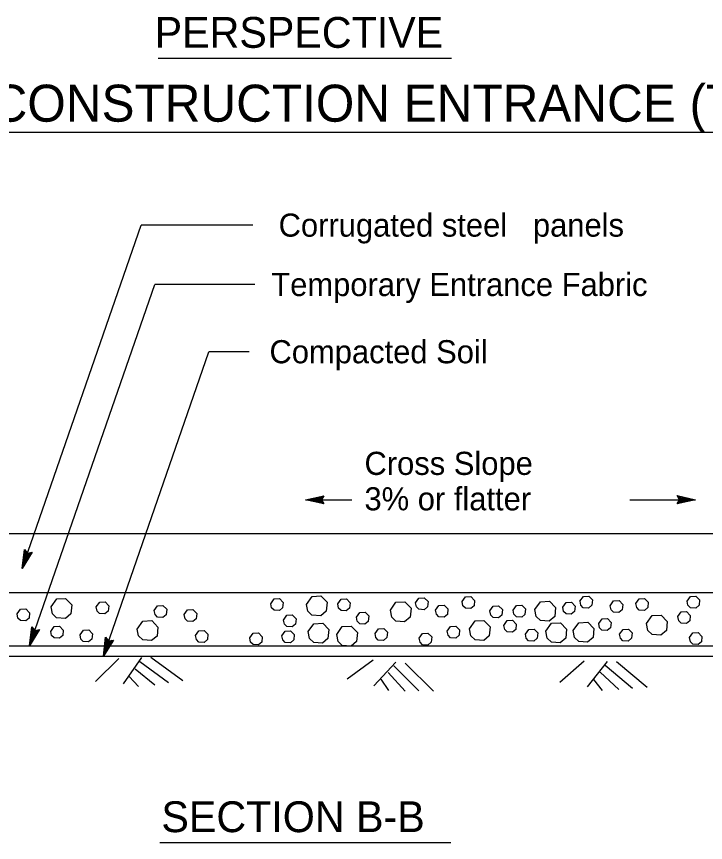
# Model space of a CAD drawing. Extents: x 6707406 to 6714471, y 1868570 to 1872341.
# Drawn here: x 6709685 to 6709899.6, y 1869786.1 to 1870043.3 of the extents above; entities that cross this region are included whole.
import ezdxf

# ---------------------------------------------------------------- set-up
doc = ezdxf.new("R2010")
doc.units = 0
for name, color, linetype in [('56 Stg 3 Anno', 7, 'Continuous'), ('57 Undefined', 7, 'Continuous'), ('59 Soundwall Ann', 7, 'Continuous'), ('60 Nongeo Data', 7, 'Continuous')]:
    doc.layers.add(name, color=color, linetype=linetype)

msp = doc.modelspace()

# ---------------------------------------------------------------- linework, layer by layer
at = {"layer": '56 Stg 3 Anno'}
for p, q in [((6709686.82, 1869871.46), (6709723.89, 1869978.35)), ((6709758.69, 1869978.35), (6709723.89, 1869978.35)), ((6709689.11, 1869847.39), (6709728.11, 1869959.86)), ((6709759.28, 1869959.86), (6709728.11, 1869959.86)), ((6709712.09, 1869844.14), (6709744.96, 1869938.93)), ((6709757.48, 1869938.93), (6709744.96, 1869938.93)), ((6709775.02, 1869892.82), (6709780.78, 1869894.1)), ((6709775.02, 1869892.82), (6709789.5, 1869892.82)), ((6709780.78, 1869891.53), (6709775.02, 1869892.82)), ((6709775.02, 1869892.82), (6709775.02, 1869892.82)), ((6709780.57, 1869891.87), (6709776.35, 1869892.82)), ((6709776.36, 1869892.82), (6709780.56, 1869893.75)), ((6709777.67, 1869892.82), (6709780.39, 1869893.42)), ((6709780.35, 1869892.22), (6709777.67, 1869892.82)), ((6709779, 1869892.82), (6709780.16, 1869893.07)), ((6709780.18, 1869892.55), (6709779, 1869892.82)), ((6709780.78, 1869894.1), (6709780.01, 1869892.82)), ((6709780.01, 1869892.82), (6709780.78, 1869891.53)), ((6709780.78, 1869894.1), (6709780.78, 1869894.1)), ((6709876.07, 1869892.82), (6709896.54, 1869892.82)), ((6709891.55, 1869892.82), (6709890.78, 1869894.11)), ((6709890.78, 1869894.11), (6709890.78, 1869894.11)), ((6709890.78, 1869894.11), (6709896.54, 1869892.82)), ((6709896.54, 1869892.82), (6709890.78, 1869891.54)), ((6709890.78, 1869891.54), (6709891.55, 1869892.82)), ((6709890.99, 1869893.76), (6709895.22, 1869892.82)), ((6709895.21, 1869892.82), (6709891.01, 1869891.89)), ((6709893.89, 1869892.82), (6709891.18, 1869892.22)), ((6709891.22, 1869893.42), (6709893.89, 1869892.82)), ((6709891.39, 1869893.09), (6709892.57, 1869892.82)), ((6709892.57, 1869892.82), (6709891.41, 1869892.56)), ((6709896.54, 1869892.82), (6709896.54, 1869892.82)), ((6709780.78, 1869891.53), (6709780.78, 1869891.53)), ((6709890.78, 1869891.54), (6709890.78, 1869891.54)), ((6709686.82, 1869871.46), (6709687.5, 1869877.32)), ((6709687.25, 1869872.72), (6709687.75, 1869876.99)), ((6709687.5, 1869877.32), (6709687.5, 1869877.32)), ((6709687.5, 1869877.32), (6709688.45, 1869876.18)), ((6709689.92, 1869876.48), (6709686.82, 1869871.46)), ((6709689.53, 1869876.4), (6709687.25, 1869872.71)), ((6709687.69, 1869873.96), (6709688.01, 1869876.72)), ((6709689.13, 1869876.3), (6709687.69, 1869873.96)), ((6709688.13, 1869875.22), (6709688.26, 1869876.4)), ((6709688.76, 1869876.25), (6709688.13, 1869875.22)), ((6709688.45, 1869876.18), (6709689.92, 1869876.48)), ((6709689.92, 1869876.48), (6709689.92, 1869876.48)), ((6709686.82, 1869871.46), (6709686.82, 1869871.46)), ((6709689.11, 1869847.39), (6709689.79, 1869853.25)), ((6709692.21, 1869852.41), (6709689.11, 1869847.39)), ((6709689.55, 1869848.65), (6709690.04, 1869852.92)), ((6709691.82, 1869852.32), (6709689.55, 1869848.64)), ((6709689.79, 1869853.25), (6709689.79, 1869853.25)), ((6709689.79, 1869853.25), (6709690.75, 1869852.1)), ((6709689.98, 1869849.89), (6709690.3, 1869852.65)), ((6709691.42, 1869852.22), (6709689.98, 1869849.89)), ((6709690.42, 1869851.14), (6709690.56, 1869852.33)), ((6709691.05, 1869852.17), (6709690.42, 1869851.14)), ((6709690.75, 1869852.1), (6709692.21, 1869852.41)), ((6709692.21, 1869852.41), (6709692.21, 1869852.41)), ((6709712.09, 1869844.14), (6709712.77, 1869850)), ((6709715.19, 1869849.16), (6709712.09, 1869844.14)), ((6709712.53, 1869845.4), (6709713.02, 1869849.67)), ((6709714.8, 1869849.08), (6709712.53, 1869845.39)), ((6709712.77, 1869850), (6709712.77, 1869850)), ((6709712.77, 1869850), (6709713.73, 1869848.86)), ((6709712.96, 1869846.65), (6709713.28, 1869849.4)), ((6709714.4, 1869848.98), (6709712.96, 1869846.65)), ((6709713.4, 1869847.9), (6709713.53, 1869849.08)), ((6709714.03, 1869848.93), (6709713.4, 1869847.9)), ((6709713.73, 1869848.86), (6709715.19, 1869849.16)), ((6709715.19, 1869849.16), (6709715.19, 1869849.16)), ((6709689.11, 1869847.39), (6709689.11, 1869847.39)), ((6709712.09, 1869844.14), (6709712.09, 1869844.14))]:
    msp.add_line(p, q, dxfattribs=at)
at = {"layer": '57 Undefined'}
for p, q in [((6709729.19, 1870030.33), (6709820.48, 1870030.33)), ((6709564.84, 1870007.33), (6709984.75, 1870007.33)), ((6709729.65, 1869786.12), (6709820.31, 1869786.12))]:
    msp.add_line(p, q, dxfattribs=at)
at = {"layer": '59 Soundwall Ann'}
for p, q in [((6709716.85, 1869843.38), (6709709.67, 1869836.26)), ((6709724, 1869843.72), (6709718.21, 1869835.47)), ((6709726.9, 1869843.84), (6709736.85, 1869836.52)), ((6709723.45, 1869842.5), (6709732.35, 1869835.95)), ((6709796.11, 1869842.93), (6709787.98, 1869836.93)), ((6709803.23, 1869842.23), (6709796.31, 1869834.91)), ((6709802.52, 1869841.1), (6709810.37, 1869833.33)), ((6709806.12, 1869841.93), (6709814.91, 1869833.24)), ((6709861.87, 1869842.56), (6709854.29, 1869835.89)), ((6709869.03, 1869842.48), (6709862.76, 1869834.59)), ((6709868.41, 1869841.29), (6709876.9, 1869834.22)), ((6709871.93, 1869842.43), (6709881.43, 1869834.52)), ((6709722.01, 1869840.23), (6709728.11, 1869835.25)), ((6709800.76, 1869839.07), (6709806.08, 1869833.26)), ((6709866.84, 1869839.12), (6709872.63, 1869833.78)), ((6709720.07, 1869837.85), (6709722.98, 1869834.65)), ((6709798.5, 1869836.99), (6709800.91, 1869833.41)), ((6709864.76, 1869836.85), (6709867.47, 1869833.49))]:
    msp.add_line(p, q, dxfattribs=at)
at = {"layer": '60 Nongeo Data'}
for p, q in [((6709602.72, 1869882.28), (6709947.32, 1869882.28)), ((6709602.72, 1869863.92), (6709756.24, 1869863.92)), ((6709756.24, 1869863.92), (6709947.32, 1869863.92)), ((6709524.37, 1869847.39), (6709755.52, 1869847.39)), ((6709755.52, 1869847.39), (6710030.98, 1869847.39)), ((6709502.72, 1869844.14), (6709754.44, 1869844.14)), ((6709754.44, 1869844.14), (6710047.92, 1869844.14))]:
    msp.add_line(p, q, dxfattribs=at)
for points in [[(6709695.81, 1869859.48), (6709697.55, 1869861.95), (6709700.33, 1869862.11), (6709702.26, 1869860.11), (6709701.98, 1869857.3), (6709700.27, 1869855.88), (6709697.52, 1869856.08), (6709696.23, 1869857.33), (6709695.81, 1869859.48)], [(6709764.23, 1869860.47), (6709765.28, 1869861.96), (6709766.94, 1869862.05), (6709768.1, 1869860.85), (6709767.93, 1869859.17), (6709766.9, 1869858.31), (6709765.26, 1869858.43), (6709764.48, 1869859.18), (6709764.23, 1869860.47)], [(6709775.34, 1869860.27), (6709777.08, 1869862.75), (6709779.86, 1869862.9), (6709781.79, 1869860.9), (6709781.51, 1869858.1), (6709779.79, 1869856.67), (6709777.05, 1869856.87), (6709775.76, 1869858.12), (6709775.34, 1869860.27)], [(6709785.07, 1869860.4), (6709786.12, 1869861.89), (6709787.78, 1869861.98), (6709788.94, 1869860.78), (6709788.77, 1869859.1), (6709787.74, 1869858.24), (6709786.1, 1869858.36), (6709785.32, 1869859.11), (6709785.07, 1869860.4)], [(6709809.33, 1869860.76), (6709810.37, 1869862.24), (6709812.04, 1869862.34), (6709813.2, 1869861.14), (6709813.03, 1869859.46), (6709812, 1869858.6), (6709810.35, 1869858.72), (6709809.58, 1869859.47), (6709809.33, 1869860.76)], [(6709823.84, 1869861.12), (6709824.89, 1869862.61), (6709826.55, 1869862.7), (6709827.71, 1869861.5), (6709827.54, 1869859.82), (6709826.51, 1869858.97), (6709824.87, 1869859.08), (6709824.09, 1869859.83), (6709823.84, 1869861.12)], [(6709860.54, 1869861.28), (6709861.59, 1869862.76), (6709863.26, 1869862.85), (6709864.41, 1869861.65), (6709864.25, 1869859.97), (6709863.22, 1869859.12), (6709861.57, 1869859.23), (6709860.8, 1869859.98), (6709860.55, 1869861.28)], [(6709869.98, 1869859.84), (6709871.02, 1869861.32), (6709872.69, 1869861.42), (6709873.85, 1869860.22), (6709873.68, 1869858.54), (6709872.65, 1869857.68), (6709871, 1869857.8), (6709870.23, 1869858.55), (6709869.98, 1869859.84)], [(6709877.95, 1869860.55), (6709879, 1869862.03), (6709880.66, 1869862.13), (6709881.82, 1869860.93), (6709881.65, 1869859.25), (6709880.62, 1869858.39), (6709878.98, 1869858.51), (6709878.2, 1869859.26), (6709877.95, 1869860.55)], [(6709893.91, 1869861.28), (6709894.95, 1869862.76), (6709896.62, 1869862.85), (6709897.78, 1869861.65), (6709897.61, 1869859.97), (6709896.58, 1869859.12), (6709894.93, 1869859.23), (6709894.16, 1869859.98), (6709893.91, 1869861.28)], [(6709685.23, 1869857.29), (6709686.28, 1869858.77), (6709687.94, 1869858.87), (6709689.1, 1869857.67), (6709688.93, 1869855.99), (6709687.9, 1869855.13), (6709686.26, 1869855.25), (6709685.48, 1869856), (6709685.23, 1869857.29)], [(6709709.89, 1869859.47), (6709710.94, 1869860.95), (6709712.6, 1869861.05), (6709713.76, 1869859.85), (6709713.59, 1869858.16), (6709712.56, 1869857.31), (6709710.92, 1869857.43), (6709710.14, 1869858.18), (6709709.89, 1869859.47)], [(6709727.94, 1869858.35), (6709728.98, 1869859.83), (6709730.65, 1869859.93), (6709731.81, 1869858.73), (6709731.64, 1869857.04), (6709730.61, 1869856.19), (6709728.96, 1869856.31), (6709728.19, 1869857.06), (6709727.94, 1869858.35)], [(6709801.48, 1869858.47), (6709803.22, 1869860.95), (6709805.99, 1869861.1), (6709807.92, 1869859.1), (6709807.64, 1869856.3), (6709805.93, 1869854.87), (6709803.19, 1869855.07), (6709801.9, 1869856.32), (6709801.48, 1869858.47)], [(6709815.55, 1869858.46), (6709816.6, 1869859.94), (6709818.26, 1869860.04), (6709819.42, 1869858.84), (6709819.25, 1869857.16), (6709818.23, 1869856.3), (6709816.58, 1869856.42), (6709815.81, 1869857.17), (6709815.56, 1869858.46)], [(6709832.49, 1869858.24), (6709833.54, 1869859.72), (6709835.2, 1869859.82), (6709836.36, 1869858.62), (6709836.19, 1869856.94), (6709835.16, 1869856.08), (6709833.52, 1869856.2), (6709832.74, 1869856.95), (6709832.49, 1869858.24)], [(6709839.71, 1869858.46), (6709840.75, 1869859.94), (6709842.42, 1869860.04), (6709843.57, 1869858.84), (6709843.41, 1869857.16), (6709842.38, 1869856.3), (6709840.73, 1869856.42), (6709839.96, 1869857.17), (6709839.71, 1869858.46)], [(6709846.49, 1869858.62), (6709848.23, 1869861.09), (6709851, 1869861.25), (6709852.94, 1869859.25), (6709852.66, 1869856.44), (6709850.94, 1869855.02), (6709848.2, 1869855.22), (6709846.91, 1869856.47), (6709846.49, 1869858.62)], [(6709855.17, 1869859.35), (6709856.22, 1869860.83), (6709857.88, 1869860.93), (6709859.04, 1869859.73), (6709858.87, 1869858.04), (6709857.84, 1869857.19), (6709856.2, 1869857.31), (6709855.42, 1869858.06), (6709855.17, 1869859.35)], [(6709737.28, 1869857.08), (6709738.33, 1869858.57), (6709739.99, 1869858.66), (6709741.15, 1869857.46), (6709740.98, 1869855.78), (6709739.96, 1869854.92), (6709738.31, 1869855.04), (6709737.54, 1869855.79), (6709737.29, 1869857.08)], [(6709768.22, 1869855.39), (6709769.26, 1869856.87), (6709770.93, 1869856.97), (6709772.09, 1869855.77), (6709771.92, 1869854.08), (6709770.89, 1869853.23), (6709769.24, 1869853.35), (6709768.47, 1869854.1), (6709768.22, 1869855.39)], [(6709790.89, 1869856.28), (6709791.94, 1869857.77), (6709793.61, 1869857.86), (6709794.76, 1869856.66), (6709794.6, 1869854.98), (6709793.57, 1869854.12), (6709791.92, 1869854.24), (6709791.15, 1869854.99), (6709790.9, 1869856.28)], [(6709881.28, 1869854.29), (6709883.02, 1869856.77), (6709885.79, 1869856.93), (6709887.72, 1869854.92), (6709887.44, 1869852.12), (6709885.73, 1869850.69), (6709882.99, 1869850.89), (6709881.7, 1869852.14), (6709881.28, 1869854.29)], [(6709891.03, 1869856.45), (6709892.07, 1869857.93), (6709893.74, 1869858.02), (6709894.9, 1869856.82), (6709894.73, 1869855.14), (6709893.7, 1869854.29), (6709892.05, 1869854.4), (6709891.28, 1869855.15), (6709891.03, 1869856.45)], [(6709722.63, 1869852.57), (6709724.37, 1869855.05), (6709727.14, 1869855.21), (6709729.07, 1869853.21), (6709728.8, 1869850.4), (6709727.08, 1869848.97), (6709724.34, 1869849.17), (6709723.05, 1869850.43), (6709722.63, 1869852.57)], [(6709775.89, 1869851.78), (6709777.63, 1869854.25), (6709780.4, 1869854.41), (6709782.33, 1869852.41), (6709782.05, 1869849.6), (6709780.34, 1869848.18), (6709777.6, 1869848.38), (6709776.31, 1869849.63), (6709775.89, 1869851.78)], [(6709826.13, 1869852.65), (6709827.87, 1869855.13), (6709830.64, 1869855.28), (6709832.57, 1869853.28), (6709832.3, 1869850.48), (6709830.58, 1869849.05), (6709827.84, 1869849.25), (6709826.55, 1869850.5), (6709826.13, 1869852.65)], [(6709836.84, 1869853.73), (6709837.89, 1869855.22), (6709839.55, 1869855.31), (6709840.71, 1869854.11), (6709840.54, 1869852.43), (6709839.52, 1869851.57), (6709837.87, 1869851.69), (6709837.1, 1869852.44), (6709836.84, 1869853.73)], [(6709849.92, 1869851.93), (6709851.66, 1869854.4), (6709854.43, 1869854.56), (6709856.37, 1869852.56), (6709856.09, 1869849.76), (6709854.37, 1869848.33), (6709851.63, 1869848.53), (6709850.34, 1869849.78), (6709849.92, 1869851.93)], [(6709858.44, 1869852.09), (6709860.18, 1869854.56), (6709862.96, 1869854.72), (6709864.89, 1869852.72), (6709864.61, 1869849.91), (6709862.89, 1869848.49), (6709860.15, 1869848.69), (6709858.86, 1869849.94), (6709858.44, 1869852.09)], [(6709866.37, 1869854.27), (6709867.41, 1869855.75), (6709869.08, 1869855.85), (6709870.24, 1869854.65), (6709870.07, 1869852.96), (6709869.04, 1869852.11), (6709867.39, 1869852.23), (6709866.62, 1869852.98), (6709866.37, 1869854.27)], [(6709695.72, 1869851.85), (6709696.76, 1869853.34), (6709698.43, 1869853.43), (6709699.59, 1869852.23), (6709699.42, 1869850.55), (6709698.39, 1869849.69), (6709696.75, 1869849.81), (6709695.97, 1869850.56), (6709695.72, 1869851.85)], [(6709704.81, 1869850.76), (6709705.86, 1869852.25), (6709707.52, 1869852.34), (6709708.68, 1869851.14), (6709708.52, 1869849.46), (6709707.49, 1869848.6), (6709705.84, 1869848.72), (6709705.07, 1869849.47), (6709704.82, 1869850.76)], [(6709740.79, 1869850.58), (6709741.84, 1869852.07), (6709743.5, 1869852.16), (6709744.66, 1869850.96), (6709744.49, 1869849.28), (6709743.47, 1869848.42), (6709741.82, 1869848.54), (6709741.05, 1869849.29), (6709740.8, 1869850.58)], [(6709757.71, 1869849.82), (6709758.75, 1869851.3), (6709760.42, 1869851.4), (6709761.58, 1869850.2), (6709761.41, 1869848.51), (6709760.38, 1869847.66), (6709758.73, 1869847.78), (6709757.96, 1869848.53), (6709757.71, 1869849.82)], [(6709767.69, 1869850.48), (6709768.73, 1869851.96), (6709770.4, 1869852.06), (6709771.55, 1869850.86), (6709771.39, 1869849.18), (6709770.36, 1869848.32), (6709768.71, 1869848.44), (6709767.94, 1869849.19), (6709767.69, 1869850.48)], [(6709784.77, 1869850.86), (6709786.51, 1869853.33), (6709789.29, 1869853.49), (6709791.22, 1869851.49), (6709790.94, 1869848.68), (6709789.22, 1869847.25), (6709786.48, 1869847.45), (6709785.19, 1869848.71), (6709784.77, 1869850.86)], [(6709796.7, 1869851.2), (6709797.74, 1869852.69), (6709799.41, 1869852.78), (6709800.57, 1869851.58), (6709800.4, 1869849.9), (6709799.37, 1869849.04), (6709797.72, 1869849.16), (6709796.95, 1869849.91), (6709796.7, 1869851.2)], [(6709810.48, 1869849.75), (6709811.52, 1869851.24), (6709813.19, 1869851.33), (6709814.35, 1869850.13), (6709814.18, 1869848.45), (6709813.15, 1869847.59), (6709811.5, 1869847.71), (6709810.73, 1869848.46), (6709810.48, 1869849.75)], [(6709819.18, 1869851.93), (6709820.22, 1869853.42), (6709821.89, 1869853.51), (6709823.05, 1869852.31), (6709822.88, 1869850.63), (6709821.85, 1869849.77), (6709820.21, 1869849.89), (6709819.43, 1869850.64), (6709819.18, 1869851.93)], [(6709843.52, 1869850.99), (6709844.56, 1869852.47), (6709846.23, 1869852.57), (6709847.39, 1869851.37), (6709847.22, 1869849.69), (6709846.19, 1869848.83), (6709844.55, 1869848.95), (6709843.77, 1869849.7), (6709843.52, 1869850.99)], [(6709872.89, 1869850.99), (6709873.94, 1869852.48), (6709875.6, 1869852.57), (6709876.76, 1869851.37), (6709876.59, 1869849.69), (6709875.56, 1869848.83), (6709873.92, 1869848.95), (6709873.14, 1869849.7), (6709872.89, 1869850.99)], [(6709894.65, 1869849.92), (6709895.7, 1869851.4), (6709897.36, 1869851.5), (6709898.52, 1869850.29), (6709898.35, 1869848.61), (6709897.33, 1869847.76), (6709895.68, 1869847.87), (6709894.91, 1869848.63), (6709894.66, 1869849.92)]]:
    msp.add_lwpolyline(points, dxfattribs=at)

# ---------------------------------------------------------------- texts
at = {"layer": '57 Undefined'}
for s, height, p in [('PERSPECTIVE', 9.6002, (6709728.05, 1870033.55)), ('TEMPORARY CONSTRUCTION ENTRANCE (TYPE 2)', 11.5203, (6709575.42, 1870010.55)), ('Corrugated steel   panels', 7.2002, (6709766.67, 1869974.75)), ('Temporary Entrance Fabric', 7.2002, (6709764.39, 1869956.26)), ('Compacted Soil', 7.2002, (6709763.82, 1869935.33)), ('Cross Slope', 7.2002, (6709793.41, 1869900.57)), ('3% or flatter', 7.2002, (6709793.41, 1869889.53)), ('SECTION B-B', 9.6002, (6709730.16, 1869789.34))]:
    msp.add_text(s, height=height, dxfattribs=at).set_placement(p)

doc.saveas('drawing.dxf')
